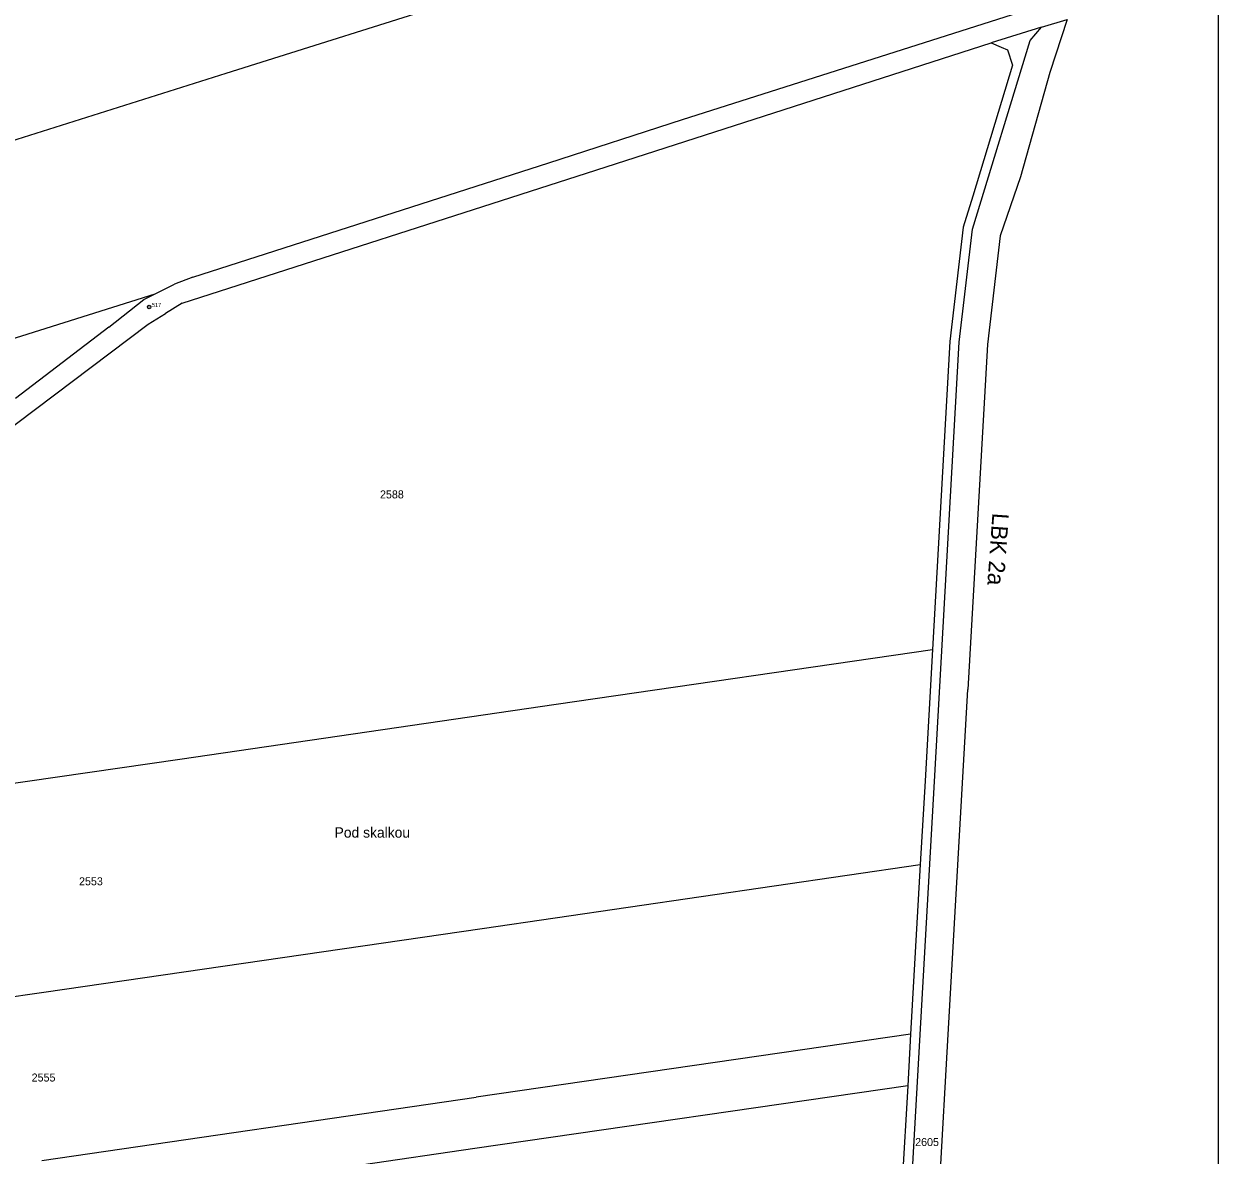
# Model space of a CAD drawing. Extents: x -565355 to -564154, y -1097649 to -1095548.
# Drawn here: x -564662 to -564155, y -1096921 to -1096441 of the extents above; entities that cross this region are included whole.
import ezdxf

# ---------------------------------------------------------------- set-up
doc = ezdxf.new("R2010")
doc.units = 0
for name, color, linetype in [('Vrstva 1', 7, 'Continuous'), ('Vrstva 13', 7, 'Continuous'), ('Vrstva 15', 7, 'Continuous'), ('Vrstva 17', 7, 'Continuous'), ('Vrstva 18', 7, 'Continuous'), ('Vrstva 24', 7, 'Continuous'), ('Vrstva 63', 7, 'Continuous')]:
    doc.layers.add(name, color=color, linetype=linetype)

msp = doc.modelspace()

# ---------------------------------------------------------------- linework, layer by layer
at = {"layer": 'Vrstva 1'}
for p, q in [((-564389.35, -1096402.76), (-564576.32, -1096461.67)), ((-564382.38, -1096481.23), (-564239, -1096435.68)), ((-564229.82, -1096442.05), (-564218.92, -1096438.69)), ((-564229.82, -1096442.05), (-564251.25, -1096448.66)), ((-564234.67, -1096447.65), (-564229.82, -1096442.05)), ((-564423.1, -1096503.98), (-564251.25, -1096448.66)), ((-564259.14, -1096527.84), (-564234.67, -1096447.65)), ((-564251.25, -1096448.66), (-564247.01, -1096450.53)), ((-564247.01, -1096450.53), (-564244.18, -1096451.69)), ((-564244.18, -1096451.69), (-564242.07, -1096458.14)), ((-564242.07, -1096458.14), (-564259.02, -1096513.75)), ((-564576.32, -1096461.67), (-564763.28, -1096520.59)), ((-564439.15, -1096499.67), (-564382.38, -1096481.23)), ((-564590.4, -1096548.26), (-564439.15, -1096499.67)), ((-564594.96, -1096559.29), (-564423.1, -1096503.98)), ((-564259.02, -1096513.75), (-564263.07, -1096527.02)), ((-564263.07, -1096527.02), (-564268.71, -1096575.5)), ((-564264.72, -1096575.85), (-564259.14, -1096527.84)), ((-564606.39, -1096555.31), (-564598.17, -1096551.14)), ((-564590.4, -1096548.26), (-564598.17, -1096551.14)), ((-564770.19, -1096606.92), (-564606.39, -1096555.31)), ((-564611.21, -1096557.69), (-564606.39, -1096555.31)), ((-564626.03, -1096569.52), (-564611.21, -1096557.69)), ((-564594.96, -1096559.29), (-564601.99, -1096563.62)), ((-564609.37, -1096568.16), (-564601.99, -1096563.62)), ((-564762.56, -1096683.78), (-564609.37, -1096568.16)), ((-564626.03, -1096569.52), (-564665.67, -1096599.71)), ((-564268.71, -1096575.5), (-564276.14, -1096706.4)), ((-564275.31, -1096762.41), (-564264.72, -1096575.85)), ((-564436.04, -1096729.65), (-564276.14, -1096706.4)), ((-564276.14, -1096706.4), (-564279.3, -1096762.12)), ((-564595.94, -1096752.9), (-564436.04, -1096729.65)), ((-564755.84, -1096776.15), (-564595.94, -1096752.9)), ((-564285.9, -1096948.97), (-564275.31, -1096762.41)), ((-564279.3, -1096762.12), (-564281.32, -1096797.75)), ((-564467.48, -1096824.82), (-564281.32, -1096797.75)), ((-564281.32, -1096797.75), (-564285.41, -1096869.77)), ((-564653.63, -1096851.88), (-564467.48, -1096824.82)), ((-564839.78, -1096878.94), (-564653.63, -1096851.88)), ((-564285.41, -1096869.77), (-564469.95, -1096896.6)), ((-564285.41, -1096869.77), (-564286.66, -1096891.66)), ((-564286.66, -1096891.66), (-564470.58, -1096918.4)), ((-564286.66, -1096891.66), (-564290.54, -1096959.99)), ((-564654.5, -1096923.44), (-564469.95, -1096896.6)), ((-564470.58, -1096918.4), (-564654.51, -1096945.14))]:
    msp.add_line(p, q, dxfattribs=at)
at = {"layer": 'Vrstva 13'}
for p, q in [((-564218.92, -1096438.69), (-564226.29, -1096461.3)), ((-564226.29, -1096461.3), (-564238.75, -1096505.56)), ((-564238.75, -1096505.56), (-564247.38, -1096530.59)), ((-564247.38, -1096530.59), (-564252.76, -1096576.88)), ((-564252.76, -1096576.88), (-564261.08, -1096723.43)), ((-564269.4, -1096869.98), (-564261.08, -1096723.43)), ((-564277.71, -1097016.43), (-564269.4, -1096869.98))]:
    msp.add_line(p, q, dxfattribs=at)
at = {"layer": 'Vrstva 24'}
for radius in [0.75, 0.0327]:
    msp.add_circle((-564608.91, -1096560.88), radius, dxfattribs=at)
at = {"layer": 'Vrstva 63'}
msp.add_line((-564154.77, -1095547.8), (-564154.77, -1097647.8), dxfattribs=at)

# ---------------------------------------------------------------- texts
at = {"layer": 'Vrstva 1'}
msp.add_text('LBK 2a', height=7, rotation=265.9064, dxfattribs=at).set_placement((-564250.62, -1096648.24))
at = {"layer": 'Vrstva 15'}
msp.add_text('Pod skalkou', height=4.4, dxfattribs=at).set_placement((-564530.13, -1096786.31))
at = {"layer": 'Vrstva 17'}
msp.add_text('517', height=1.7, dxfattribs=at).set_placement((-564607.72, -1096560.87))
at = {"layer": 'Vrstva 18'}
for s, p in [('2588', (-564510.85, -1096642.19)), ('2553', (-564638.71, -1096806.54)), ('2555', (-564658.85, -1096889.89)), ('2605', (-564283.49, -1096917.3))]:
    msp.add_text(s, height=3.4, dxfattribs=at).set_placement(p)

doc.saveas('drawing.dxf')
